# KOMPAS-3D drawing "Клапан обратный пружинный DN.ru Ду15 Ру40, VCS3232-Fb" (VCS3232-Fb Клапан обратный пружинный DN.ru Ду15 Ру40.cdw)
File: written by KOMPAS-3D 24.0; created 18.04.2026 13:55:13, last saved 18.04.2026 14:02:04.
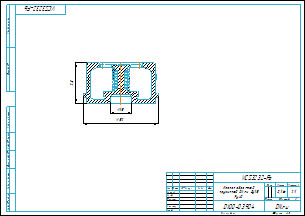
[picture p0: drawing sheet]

Document properties: c3d_UniqueCompID: 071bd168-1a06-425c-849c-e99e84a96128; Наименование: Деталь; Автор: 712; Класс точности: c; Знак неуказанной шероховатости: Шероховатость не задана; Рассекать на разрезах: Да; Автор: 712; Форматы листов документа: A3; Полное имя файла: VCS3232-Fb Клапан обратный пружинный DN.ru Ду15 Ру40.m3d; Масса: 0.16; Наименование: Клапан обратный пружинный DN.ru Ду15 Ру40; Количество листов документа: 1; Примечание: D100-03904

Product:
- Body: Тело 1  | qty 1
    Масса: 0.17889
- Part/product: Клапан обратный пружинный DN.ru Ду15 Ру40  | designation VCS3232-Fb
    Масса: 0.16
    Раздел спецификации: Прочие изделия
    Примечание: D100-03904
    additional columns: 071bd168-1a06-425c-849c-e99e84a96128; Деталь; 712; c; Шероховатость не задана; Да

Views: Вид 1, Местный разрез 1, Спереди
Referenced files in C:\Users\712\Desktop\Новая папка (4)\: VCS3232-Fb Клапан обратный пружинный DN.ru Ду15 Ру40.m3d
Referenced files in C:\Users\Пупс\Desktop\Работа\Работа\проверка\VCS3232-Fb WDVF Ду15-200 Ру40-25 Клапан обратный пружинный DN.ru\Ду15\: VCS3232-Fb Клапан обратный пружинный DN.ru Ду15 Ру40.cdw
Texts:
  Линейный размер
  VCS3232-Fb
  Клапан обратный
  пружинный DN.ru Ду15
  Ру40
  Клапан обратный пружинный DN.ru Ду15 Ру40
  VCS3232-Fb Клапан обратный пружинный DN.ru Ду15 Ру40
Dimensions and other numbers on the sheet: 0; 3; 2; 4; 52; 15; 28; 2:1; 1; 0,16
